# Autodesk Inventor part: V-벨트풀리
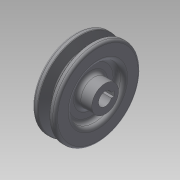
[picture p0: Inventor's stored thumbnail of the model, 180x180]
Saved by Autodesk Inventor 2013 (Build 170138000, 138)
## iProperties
Created: 2015-02
Part Number: V-벨트풀리
Material: 일반
Document SubType Name: Modeling
Designer: Administrator
Density: 1 g/cm^3
Author: Administrator
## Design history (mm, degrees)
sketch "스케치1"
  geometry: L1 (0, 0)-(25, 0); L2 (25, 0)-(25, 11); L3 (25, 11)-(13, 11); L4 (13, 11)-(13, 21.5); L5 (13, 21.5)-(19, 21.5); L6 (19, 21.5)-(19, 35.2); L7 (19, 35.2)-(14.325, 35.2); L8 (14.325, 35.2)-(11.574, 26.2); L9 (11.574, 26.2)-(7.426, 26.2); L10 (7.426, 26.2)-(4.675, 35.2); L11 (4.675, 35.2)-(0, 35.2); L12 (0, 35.2)-(0, 21.5); L13 (0, 21.5)-(6, 21.5); L14 (6, 21.5)-(6, 11); L15 (6, 11)-(0, 11); L16 (0, 11)-(0, 0); L17 (5.5, 32.5)-(13.5, 32.5)
  constraints: 34 end point, 12 parallel, 3 collinear, 2 equal length, 2 perpendicular, 2 point on line, 1 horizontal, 1 vertical alignment
  dimensions: "d0" = 25 distance of L1.start L1.end; "d1" = 19 distance between parallel lines of L6 L12; "d3" = 22 diameter of L3 L1; "d4" = 8 distance of L17.start L17.end; "d5" = 34 deg angle of L8 L10; "d6" = 6 distance between parallel lines of L14 L12; "d7" = 6 distance between parallel lines of L6 L4; "d8" = 43 diameter of L13 L1; "d9" = 2.7 distance between parallel lines of L7 L17; "d10" = 6.3 distance between parallel lines of L9 L17; "d11" = 65 diameter of L17 L1
revolve "회전1" sketch "스케치1" stored, may be unused: angle "d12" = 90 deg
sketch "스케치2"
  geometry: L1 (-2, 5.123)-(-2, 7.3); L2 (-2, 7.3)-(2, 7.3); L3 (2, 7.3)-(2, 5.123); C1 r 11 at (0, 0) reference; A1 r 5.5 centre (0, 0) between (-2, 5.123) and (2, 5.123); 1 further point
  constraints: 6 end point, 2 point on circle, 1 centre point, 1 coincident, 1 midpoint, 1 parallel, 1 perpendicular, 1 vertical, 1 vertical alignment
  dimensions: "d13" = 11 diameter of A1; "d16" = 12.8 dimension on A1 L2; "d17" = 4 distance of L1.end L2.end
extrude "돌출1" cut sketch "스케치2" stored distance "d18" = 10; taper "d19" = 0 deg
fillet "모깎기1" dims "d20" = 2, "d21" = 0.5, "d22" = 1, "d23" = 3
node "솔리드1"
